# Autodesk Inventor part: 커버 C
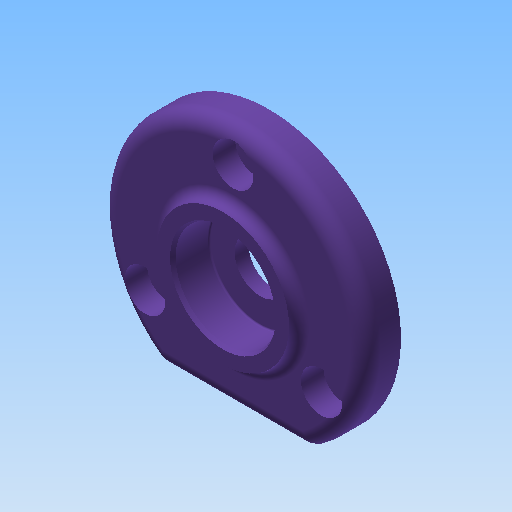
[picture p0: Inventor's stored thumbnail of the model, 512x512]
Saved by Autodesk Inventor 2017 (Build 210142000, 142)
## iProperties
Created: 2020-04
Part Number: 커버 C
Material: 알루미늄 6061
Document SubType Name: Modeling
Designer: mduedu
Density: 2.71 g/cm^3
Appearance: 보라색
Mass: 35.2376 g
Surface Area: 62.3739 cm^2
Volume: 13.0028 cm^3
Author: mduedu
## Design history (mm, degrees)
sketch "스케치1"
  geometry: C1 r 26 at (0, 0); 1 further point
  constraints: 1 centre point, 1 coincident
  dimensions: "d0" = 52 diameter of C1
extrude "돌출1" new body sketch "스케치1" distance "d1" = 7; taper "d2" = 0 deg
sketch "스케치2"
  geometry: L1 (-14.62, -21.5)-(14.62, -21.5); A1 r 26 centre (0, 0) between (-14.62, -21.5) and (14.62, -21.5) reference; 1 further point
  constraints: 2 end point, 2 point on circle, 1 horizontal
  dimensions: "d3" = 21.5 distance from line of L1 point (0, 0)
extrude "돌출2" cut sketch "스케치2" stored distance "d4" = 7; taper "d5" = 0 deg
sketch "스케치6"
  geometry: C1 r 13 at (0, 0); 1 further point
  constraints: 1 centre point, 1 coincident
  dimensions: "d29" = 26 diameter of C1
extrude "돌출5" join sketch "스케치6" distance "d30" = 2; taper "d31" = 0 deg
fillet "모깎기1" dims "d6" = 3
fillet "모깎기2" dims "d7" = 3
fillet "모깎기4" dims "d33" = 2
sketch "스케치3" dims "d8" = 40
  geometry: 3 further points
  constraints: 2 vertical alignment, 1 coincident, 2 other
hole "구멍1" sketch "스케치3" at (0, 20) diameter "d9" = 4.5; stored, may be unused: countersink angle "d13" = 90 deg, drill point angle "d15" = 118 deg; dims "d10" = 6, "d11" = 8, "d12" = 4.4, "d14" = 8
sketch "스케치4"
  geometry: C1 r 14 at (0, 0); 1 further point
  constraints: 1 centre point, 1 coincident
  dimensions: "d19" = 28 diameter of C1
extrude "돌출3" join sketch "스케치4" distance "d20" = 4; taper "d21" = 0 deg
sketch "스케치5"
  geometry: C1 r 12 at (0, 0); 1 further point
  constraints: 1 centre point, 1 coincident
  dimensions: "d22" = 24 diameter of C1
extrude "돌출4" cut sketch "스케치5" distance "d23" = 3; taper "d24" = 0 deg
fillet "모깎기3" dims "d25" = 3
chamfer "모따기1" distance "d26" = 0.5; stored, may be unused: second distance "d27" = 2, angle "d28" = 45 deg
sketch "스케치7"
  geometry: 2 further points
  constraints: 1 coincident
hole "구멍2" sketch "스케치7" at (0, 0) diameter "d34" = 10; stored, may be unused: countersink angle "d38" = 90 deg, drill point angle "d40" = 118 deg; dims "d35" = 6, "d36" = 20, "d37" = 7.3, "d39" = 8
fillet "모깎기5" dims "d41" = 0.3
chamfer "모따기2" distance "d42" = 0.7; stored, may be unused: second distance "d43" = 2, angle "d44" = 30 deg
node "솔리드1"
pattern_circular "원형 패턴1" dims angle "d17" = 360 deg
node "투영된 루프1"
